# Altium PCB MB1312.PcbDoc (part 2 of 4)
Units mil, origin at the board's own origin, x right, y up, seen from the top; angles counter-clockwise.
Board outline 2755.91 x 5249.6 mil, 6 copper layers (Top Layer, GND, Signal, PWR, GND (Mid2), Bottom Layer), stack 74.545 mil thick; 297 components, 280 nets, 1142 pads, 623 vias.
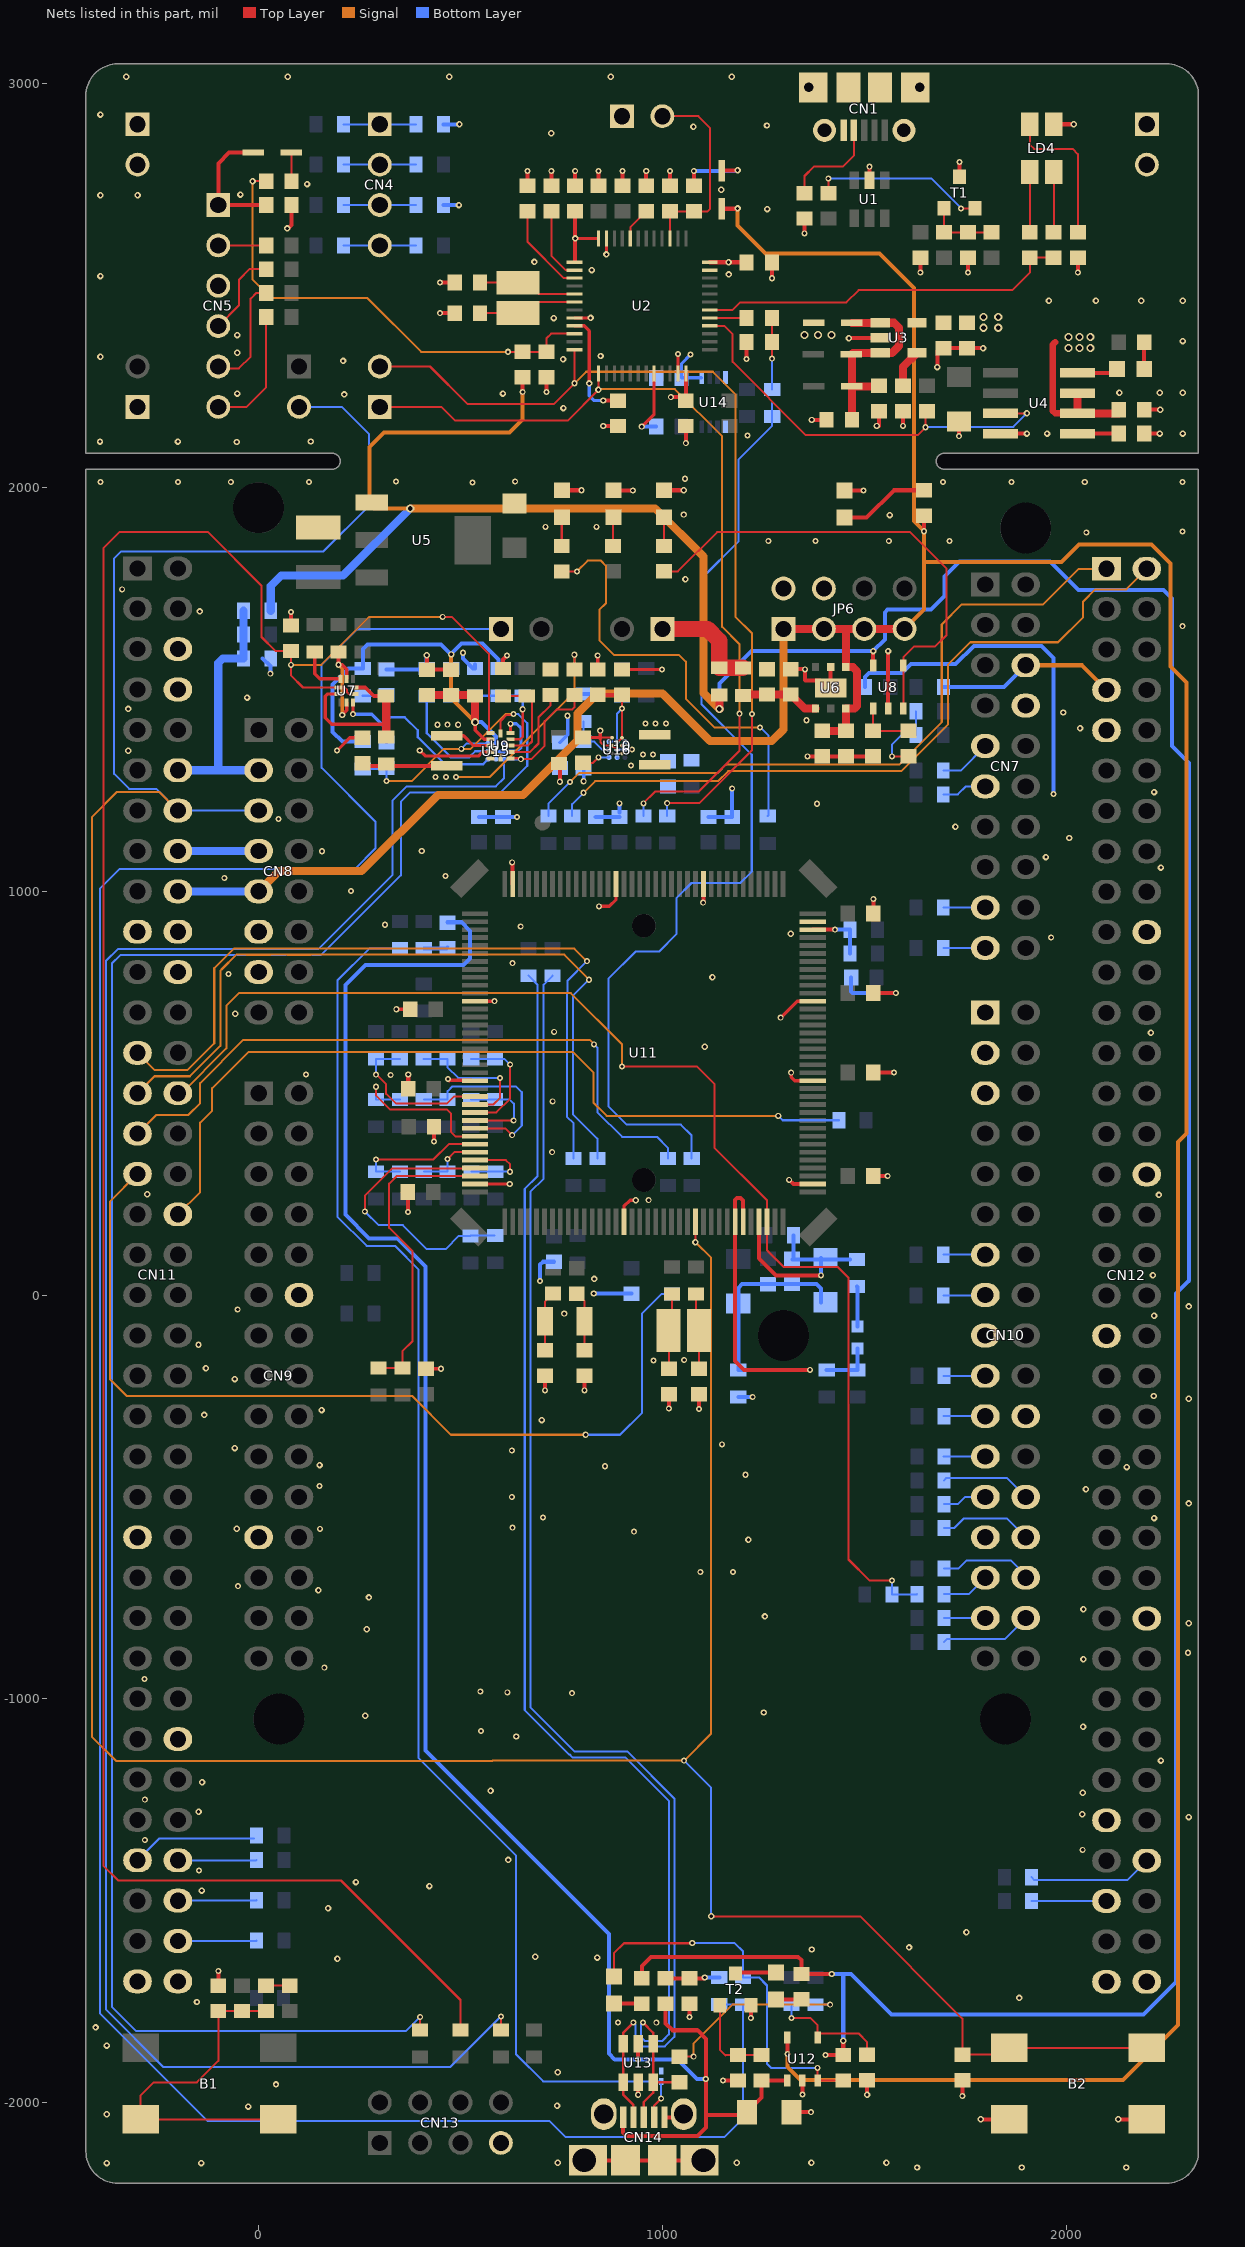
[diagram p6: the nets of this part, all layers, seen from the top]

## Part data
B1 B2: library part "SW PUSHBUTTON", "SE PUSHBUTTON"
C1 C2 C3 C4 C5 C6 C7 C8 C10 C11 C12 C13 C20 C26: library part Capacitor_ST, "Capacitor 0402 / 0603 / 0805"
C9 C14 C19 C27 C60: library part "CAP SMD 0603  X5R 1µF 25V 10%", "0603  X5R 1µ"
C15: library part "CAP SMD 0603  X7R 10000PF 50V 10%", "0603  X7R 10NF"
C16 C17 C18 C42: library part "Cap Pol1", "Polarized Capacitor (Radial)"
C21 C22 C25 C28 C29 C30 C31 C32 C33 C34 C39 C46 C47 C49 C50 C51 C53 C55 C57 C58 C61: library part Cap, "Capacitor"
C23 C24 C48: library part CAP_CC0603KRX7R9BB104, "Capacitor SMD 0603 100000pF X7R 50V +/-10%"
C35 C36 C37 C38 C40 C41: library part CAP, "Capacitor"
C43 C44 C45: library part Cap, "Capacitor,100nF,10%,16V,X7R,0603,YAGEO"
C52 C54: library part "CAP SMD 0603  X5R 1µF 25V 10%", "0603  X5R 4.7uF"
C56 C59: library part "Cap Pol1", "Tan Capacitor,1uF,10%,16V,Tan-A,TAJA105K016R"
CN2 CN3 CN6 JP1 JP2 JP3 JP4 JP5: library part JP2
CN4: "Header, 4-Pin, Single row"
CN5: "Header, 6-Pin, Single row"
CN7: "Header, 10-Pin, Dual row,female"
CN8: "Header, 8-Pin, Dual row,female"
CN9: "Header, 15-Pin, Dual row,female"
CN10: "Header, 17-Pin, Dual row,female"
CN11 CN12: "Header, 36-Pin, Dual row"
CN13: library part "Header 4X2_CN", "Header, 4-Pin, Dual row"
D2: library part Diode, "Default Diode"
D6: "Zener Diode ESDALC6V1-1U2"
JP6: "Header, 4-Pin, Dual row"
L1 L2 L3: library part Inductor, "Inductor"
LD1 LD2 LD3 LD5 LD6 LD7 LD8: library part LED2, "Typical RED, GREEN, YELLOW, AMBER GaAs LED"
LD4: "Bicolor Led"
R1 R2 R3 R4 R5 R7 R9 R10 R12 R13 R14 R15 R16 R18 R19 R20 R21 R23 R24 R25 R26 R27 R28 R50 R54: library part Resistor_ST, "Resistor 0402 / 0603 / 0805"
R6 R8 R11 R17 R22 R29 R30 R31 R32 R33 R34 R39 R40 R43 R44 R45 R52: library part Res1, "Resistor"
R35 R36 R37 R38 R41 R42 R46 R47 R48 R49 R51 R53: library part res1, "Resistor"
SB5 SB6 SB100 SB102 SB104 SB106 SB112 SB114 SB122 SB124 SB125 SB126 SB128 SB130 SB131 SB132 SB133 SB136 SB137 SB140 SB141 SB142 SB143 SB144 SB147 SB149 SB150 SB152 SB154 SB155 SB156 SB157 SB158 SB159 SB166 SB168 SB169 SB170 SB177 SB179 SB180 SB182 SB188 SB191 SB192 SB193 SB194 SB195 SB196 SB197: library part "Circuit Breaker_close", "Circuit Breaker"
SB12 SB13 SB19 SB101 SB103 SB105 SB107 SB108 SB109 SB110 SB111 SB113 SB116 SB119 SB120 SB121 SB123 SB127 SB129 SB145 SB146 SB148 SB151 SB153 SB167 SB178: library part "Circuit Breaker", "Circuit Breaker"
T1 T2: library part NPN, "NPN Bipolar Transistor"
TP1: library part TP
U2: "Medium-density performance line ARM-based 32-bit MCU with 64KB Flash"
U3: "200 mA low quiescent current very low noise LDO"
U5: library part LD1117
U6: library part LD39050P
U7: "Low voltage 0.5 O max dual SPDT switch with break-before-make"
U9: library part ST1PS022D1QTR, "400mA Nano-Quiescent?Synchronous step-down converter  with voltage selection, power good, Aux Switch"
U10: library part ST1PS01FJR, "400mA Nano-Quiescent?Synchronous step-down converter  with voltage selection and power good"
U12: library part STMPS2141STR
U15 U16: library part ADP5301, "UL Step down regulator"
X1 X3: library part XTAL, "Crystal Oscillator"
X2: library part CRYSTAL_32K, "Crystal"

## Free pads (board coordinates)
  round 125.98 hole 125.98 unplated: 0(0,1950) 0(50,-1050) 0(1300,-100) 0(1850,-1050) 0(1900,1900)

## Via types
v1: diameter 15, hole 8, Top Layer to Bottom Layer, tented both sides, 405 vias
v2: diameter 16, hole 8, Top Layer to Bottom Layer, tented both sides, 179 vias
v3: diameter 20, hole 12, Top Layer to Bottom Layer, tented both sides, 39 vias

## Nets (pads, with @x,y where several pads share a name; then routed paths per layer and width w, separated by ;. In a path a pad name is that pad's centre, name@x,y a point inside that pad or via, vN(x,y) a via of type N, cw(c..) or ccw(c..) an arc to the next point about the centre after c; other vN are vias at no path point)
+3V3: CN8.7 CN11.16 JP5.1 SB5.1 SB6.2 SB111.1 | length 523.8
  Top Layer w40: JP5.1@1000,1650 1111.85,1650 1141,1620.85 SB5.1@1141,1553.75 SB6.2@1199,1553.75
  Bottom Layer w10: 10,1577 29,1558 v1(29,1539.25)
  Bottom Layer w20: CN11.16@-200,1100 CN8.7@0,1100
+3V3_PER: R23.1 R41.2 R45.2 R51.1 SB5.2 SB110.1 U8.5 | length 9073.1
  Top Layer w10: v1(654,2236.7) R23.1@654,2273.2 ; R45.2@949,-1692.5 949,-1662 972,-1639 1336.5,-1639 1345.01,-1647.51 R41.2@1345.01,-1681.5 v1(1419.5,-1681.5) ; v1(1404,-1882) 1404.5,-1882.5 R51.1@1448,-1882.5 v1(1448,-1847) ; U8.5@1522.09,1559.15 v2(1522.09,1595)
  Top Layer w20: SB5.2@1140.75,1486 SB5.2@1141,1486.25 v3(1141,1452)
  Signal w10: v3(375.5,1948.5) 286.5,1948.5 275,1960 275,2100.94 310.06,2136 621.5,2136 654,2168.5 v1@654,2235
  Signal w20: v3(375.5,1948.5) 982.26,1948.5 1101.73,1829.03 1101.73,1491.27 v3(1141,1452)
  Bottom Layer w10: v3(1141,1452) 1141,1515 1221,1595 v2(1522.09,1595) 1551,1623.91 1551,1691 1558,1698 1665,1698 1699,1732 1699,1780 1736,1817 1960,1817 2031,1746 2241,1746 2262,1725 2262,1360.19 2304.5,1317.69 2304.5,35.5 2272.4,3.4 2272.4,-1701.6 2192,-1782 1568,-1782 1467.5,-1681.5 v1(1419.5,-1681.5) ; v1(1448,-1847) 1448,-1683.5
  Bottom Layer w20: SB110.1@30,1695 30,1756 56,1782 209,1782 v3(375.5,1948.5)
+3V3_ST_LINK: C1.2 C3.2 C8.2 C9.1 C12.2 C13.2 C43.2 JP1.1 R5.2 R13.2 SB101.2 T1.3 U2.1 U2.9 U2.24 U2.36 U2.48 U3.5 U14.1 | length 962.9
  Top Layer w8: U2.9@782.68,2400.79 806.41,2400.79 819,2388.2 v2(819,2258) ; v2(784,2617.27) 784.06,2617.32 U2.48@841.73,2617.32
  Top Layer w10: U2.1@784,2559.53 v2(784,2617.27) C1.2@784,2684.45 ; R5.2@842,2747.5 v1(842,2784) ; v1(853.5,2215.5) C12.2@890,2215.5 ; v1(1021,2224) 1049.5,2224 C13.2@1058,2215.5 ; C13.2@1058.27,2215.71 U2.24@1058.27,2282.68 ; U2.36@1117.32,2558.27 1208.24,2558.27 C3.2@1208.5,2558 v2@1170.27,2558 ; T1.3@1736,2770.37 v1(1736,2806.87) ; v1(2029,2533) R13.2@2029,2569.5
  Bottom Layer w8: v2(819,2258) 819,2227.5 831,2215.5 v1(853.5,2215.5) ; v1(1070,2330) 1047.5,2307.5 C43.2@1047.5,2272 U14.1@1096.23,2272
  Bottom Layer w10: SB101.2@457.75,2900 v2(497.25,2899.94)
  other v2: 1164,2558
  other v3: 1795,2396 1832,2396 1795,2423 1832,2423
+5V: C26.2 C27.1 CN8.9 CN11.18 D2.1 JP6.1 JP6.3 JP6.5 JP6.7 R28.2 U6.1 U6.6 U12.5 | length 9925.8
  Top Layer w10: D2.1@1147,2690.76 v2@1185.61,2690.76 ; v1(1309.6,-1879.54) U12.5@1309.6,-1838.85 ; v1(1648,1892) R28.2@1648,1930.5
  Top Layer w20: JP6.1@1300,1650 JP6.3@1400,1650 1454,1650 ; C26.2@1396,1397.5 C27.1@1455,1397.5 U6.6@1455,1452.22 ; U6.6@1454.4,1452.82 1475.82,1452.82 1482,1459 1482,1545 1471.82,1555.18 U6.1@1454.4,1555.18 1454.4,1649.6 1454,1650 ; JP6.7@1600,1650 JP6.5@1500,1650 1454,1650
  Signal w10: v2(1186.37,2691.51) 1186.37,2649.63 1256,2580 1538,2580 1623,2495 1623,1917 v1(1648,1892) 1648,1816 ; v1(1309.6,-1879.54) 1309.6,-1911.58 1342.02,-1944 2141,-1944 2277,-1808 2277,379 2298.7,400.7 2298.7,1517.3 2259,1557 2259,1812 2212,1859 2032,1859 1989,1816 1648,1816 ; JP6.7@1600,1650 1648,1698 1648,1816
  Signal w20: CN11.18@-200,995.6 CN11.18@-200,1000 ; CN8.9@-4.4,995.6 CN8.9@0,1000 50,1050 255,1050 444,1239 655,1239 790.13,1374.13 790.13,1440.87 839.26,1490 1000,1490 1118,1372 1271,1372 1300,1401 JP6.1@1300,1650 JP6.3@1400,1650 JP6.5@1500,1650 JP6.7@1600,1650
  Bottom Layer w20: CN11.18@-200,995.6 CN11.18@-200,1000 -8.8,1000 -4.4,995.6 CN8.9@0,1000
AGND: C45.2 C56.2 C57.2 C58.2 C59.2 CN10.3 CN12.32 SB166.2 U11.30 U11.31 | length 2170.9
  Top Layer w10: U11.31@1200.06,181.69 1200.06,233.94 1194,240 1185.01,240 1180.38,235.37 U11.30@1180.38,181.69 1180.38,-162.88 1202.75,-185.25 v1(1365.52,-185.25)
  Bottom Layer w10: v1(1365.52,-185.25) SB166.2@1188,-185.25 C56.2@1188,-20.5 1188,17.75 1197.55,27.3 C58.2@1321,27.3 1381.7,27.3 1393,16 C59.2@1393,-18.5 ; C45.2@1501.75,1506 1501.75,1530.52 1511.92,1540.69 1593.88,1540.69 1615.79,1562.6 1726.6,1562.6 1772,1608 1938.88,1608 1969,1577.88 v1(1969,1241)
AIN_1: R1.2 R23.2 R24.2 U2.10 | length 1188
  Top Layer w5: v2(-15,2759) R1.2@18.5,2759 ; v2(617.6,2336.2) R23.2@654,2336.2 R24.2@713,2336.2 713,2369.89 724.53,2381.42 782.68,2381.42 U2.10@782.68,2381.1
  Signal w5: v2(-15,2759) -15,2515 30.31,2469.69 268.84,2469.69 402.33,2336.2 v2(617.6,2336.2)
AVDD: C58.1 C59.1 CN10.1 SB149.1 SB152.2 U11.33 | length 506.5
  Top Layer w10: U11.33@1239.43,181.69 1239.5,181.63 1239.5,91.18 1281.68,49 v1(1393,49)
  Bottom Layer w10: SB149.1@1324.75,148 1324.75,90.45 1322.8,88.5 C59.1@1393,88.5 ; v1(1393,49) C59.1@1393,88.5 ; C59.1@1393,91.5 C59.1@1393,88.5 ; SB152.2@1465,88.5 C59.1@1393,88.5
E5V: CN11.6 D3.1 JP6.2
  other v3: 1352,2378 1385.5,2378 1419,2378
GND: B2.1 B2.4 C1.1 C2.1 C3.1 C4.1 C5.2 C6.2 C7.2 C8.1 C9.2 C10.1 C11.1 C12.1 C13.1 C14.1 C15.1 C16.2 C17.2 C18.2 C19.2 C20.1 C21.1 C22.1 C23.2 C24.2 C25.1 C26.1 C27.2 C28.2 C29.2 C30.2 C31.2 C32.2 C33.2 C34.2 C35.2 C36.2 C37.2 C38.2 C39.1 C41.1 C42.2 C43.1 C44.2 C46.1 C47.1 C48.2 C49.2 C50.2 C51.2 C52.2 C53.2 C54.2 C55.1 C60.2 C61.2 CN1.5 CN1.6 CN1.7 CN1.8 CN1.9 CN1.10 CN1.11 CN2.1 CN2.2 CN3.1 CN3.2 CN5.3 CN7.8 CN8.11 CN8.13 CN9.12 CN9.23 CN10.5 CN10.17 CN10.22 CN10.27 CN11.8 CN11.19 CN11.20 CN11.22 CN11.49 CN11.60 CN11.71 CN11.72 CN12.9 CN12.20 CN12.39 CN12.54 CN12.63 CN12.71 CN12.72 CN13.7 CN14.5 CN14.6 CN14.7 CN14.8 CN14.9 CN14.10 CN14.11 D6.2 JP2.1 LD1.2 LD2.2 LD3.2 LD4.1 LD6.2 R2.2 R3.1 R4.1 R6.2 R7.1 R10.2 R17.1 R24.1 R27.1 R32.2 R33.1 R35.1 R36.2 R38.2 R42.2 R47.2 R48.1 R52.1 R53.1 SB9.1 SB105.2 SB114.1 SB115.1 SB125.1 SB166.1 T2.2 U1.2 U2.8 U2.20 U2.23 U2.35 U2.47 U3.2 U4.4 U5.1 U6.0 U6.2 U7.8 U8.2 U9.4 U9.11 U10.A1 U10.C1 U10.D2 U11.16 U11.38 U11.51 U11.61 U11.71 U11.83 U11.94 U11.107 U11.120 U11.130 U11.143 U12.2 U13.2 U14.4 U14.5 U15.B1 U15.B2 U16.B1 U16.B2 | length 6306.4
  Top Layer w5: 846.15,1378.09 846.15,1369.85 854.9,1361.1 U10.C1@875.4,1361.1 876.32,1361.1 881.47,1355.94 883,1355.94 U10.D2@887.69,1351.26 ; 846.15,1380.78 U10.A1@875.4,1380.78
  Top Layer w8: v1(194,1348.75) 225.5,1380.25 C21.1@257.53,1380.25 ; v1(233.75,1438.75) U7.8@233.75,1467.47 ; v1(341,708) C29.2@375.5,708 ; v1(399,1348.75) 412.25,1335.5 545.5,1335.5 555.25,1345.25 U9.4@574.39,1345.25 ; C39.1@415,-182.5 v1(451.57,-182.5) ; v1@472.12,531.88 U11.130@526.71,531.88 ; U11.143@535.69,275.2 v1(622.02,275.2) v1@622.82,276 ; U11.120@535.69,727.95 v1(583.95,727.95) ; U9.11@623.61,1392.5 v1(623.61,1415) ; U2.8@782.68,2420.47 v2(822.18,2420.41) v2(822.18,2420.41) ; R35.1@803,1381.25 845.69,1381.25 ; C24.2@839.83,1549.75 v1(839.83,1584.13) ; v1(843,963) 868.84,963 885.1,979.26 U11.94@885.1,1018.31 ; 846.15,1378.09 846.15,1380.78 v1(846.15,1398.01) ; v2(861.42,2577.76) U2.47@861.42,2617.32 ; C25.1@900.31,1549.75 v1(999.25,1549.75) ; U11.16@904.79,181.69 904.79,219.79 920,235 v2(934,235) ; v1(948.98,2151) 979.53,2181.55 U2.20@979.53,2282.68 ; U2.23@1038.58,2282.68 v1@1038.58,2330.58 ; v1(1293,687) 1333.95,727.95 U11.61@1372.31,727.95 ; v1(1319,550.79) 1319,540 1327.9,531.1 U11.51@1372.31,531.1
  Top Layer w10: R42.2@-100,-1710.5 v1(-100,-1674) ; v2@73,2642 81.5,2650.5 R2.2@81.5,2700 ; R32.2@80,1658.5 v1(80,1692) ; C33.2@369.5,255 370,254.5 v1(370,206) ; C31.2@370.5,511 v1(370.5,546.02) ; v2@416.59,1584.71 C22.1@416.59,1549.25 C23.2@476.84,1549.25 ; v1(434.5,380.1) R38.2@434.5,417 ; v1(449,2432) C6.2@485.5,2432 ; v1(449,2508) C5.2@485.5,2508 ; v1(469,535) v1@472.12,531.88 ; SB9.1@605,1551.75 605,1574 v1(615,1584) ; U11.107@629.2,1018.31 v1@629.2,1070.79 ; R4.1@666,2747.5 v1(666,2784) ; v1(709,-236) C35.2@709,-199.5 ; v1(713,2236.7) R24.1@713,2273.2 ; R3.1@725,2747.5 v1(725,2784) ; LD3.2@752.75,1993.46 v1(799.75,1993.43) ; C1.1@784,2747.5 v1(784,2784) ; CN14.7@806.36,-2143.09 CN14.8@908.72,-2143.09 CN14.9@999.28,-2143.09 CN14.10@1101.64,-2143.09 ; v1(807,-236) C36.2@807,-199.5 ; v1(853.5,2152.5) C12.1@890,2152.5 ; CN14.6@866.4,-2024.2 CN14.6@879.2,-2037 ; LD2.2@879.76,1993 v1@926.73,1993 ; C2.1@901,2747.5 v1(901,2784) ; v1(940,-1980.74) U13.2@940,-1949.24 ; R7.1@960,2747.5 v1(960,2784) ; CN14.5@1005.18,-2036.79 1044.94,-2036.79 CN14.11@1052.82,-2028.91 ; LD1.2@1006,1993.47 v1@1052.97,1993.47 ; v1(1016,-281) C37.2@1016,-244.5 ; R6.2@1019,2747.5 v1(1019,2784) ; v1(1058,2110) C13.1@1058,2152.5 ; v1(1067,-1788) R47.2@1067,-1755.5 ; v1(1091,-282) C38.2@1091,-245.5 ; v1@1101.64,972.36 U11.83@1101.64,1018.31 ; v1(1150,-1945.55) 1150.05,-1945.5 R48.1@1187,-1945.5 ; v1(1208.5,2318.76) C7.2@1208.5,2361 ; v1(1219,-1791) 1219.59,-1790.41 T2.2@1219.59,-1759.37 ; v2(1271.5,2518.5) C3.1@1271.5,2558 ; v1(1314,285.5) 1324.3,275.2 U11.38@1372.31,275.2 ; C19.2@1318,1550.5 v1@1353,1550.5 ; C42.2@1320,-2024 v1(1368.36,-2024) ; v1(1347,-1980) U12.2@1347,-1945.15 ; v1(1352,2630) R10.2@1352,2666.5 ; 1353,1523.5 v1(1353,1550) v1@1354.5,1548.5 ; 1354.5,1522 U6.0@1391,1522 ; v1(1359.5,1334.5) C26.1@1396,1334.5 R36.2@1522,1334.5 ; v1(1370,2168) C10.1@1406.5,2168 ; U6.0@1417,1504 U6.2@1417,1555.18 ; LD6.2@1451.04,1992.79 v1(1498.04,1992.77) ; v2@1462,2371 U3.2@1531.85,2371 ; R52.1@1506.68,-1944.5 1506.68,-1980.68 v2(1507,-1981) ; U1.2@1513,2761.24 v1(1513,2795) ; C34.2@1522.5,295 v1(1558,295) ; C32.2@1522.5,551 v1(1574,551) ; C30.2@1522.5,748 v1(1578.18,748) ; C28.2@1522.5,945 v1@1522.5,980.5 ; v1(1531,2153) 1537,2153 C14.1@1537,2189.5 ; v2(1559,1595) 1559,1453.35 U8.2@1559.5,1452.85 ; v1(1596,2153) C15.1@1596,2189.5 ; v1(1639,2533) C4.1@1639,2569.5 ; v2(1681,2298.5) C8.1@1681,2338 ; C8.1@1696,2345.5 C9.2@1755,2345.5 v2(1794.5,2345.5) ; v1(1735,2127.5) C16.2@1735,2164 ; v1(1743,-1984) C41.1@1743,-1944.5 ; v1(1756.7,2533) R17.1@1756.7,2569.5 ; v2(1788.87,-2041.58) B2.1@1858.72,-2041.58 ; U4.4@1837.53,2134 v2(1903,2134) ; LD4.1@1969.53,2900.06 v2(2018.94,2900.06) ; v2(2129.42,-2041.58) B2.4@2199.28,-2041.58 ; R27.1@2193.5,2134 v2(2232,2134) ; C11.1@2193.5,2193 v2(2233,2193)
  Bottom Layer w5: U16.B2@887.69,1351.26 U16.B1@907.37,1351.26 v1(924.74,1351.26) v1@925,1351
  Bottom Layer w8: v1(233.75,1438.75) 280.25,1438.75 317,1402 C48.2@317,1368.5 ; U15.B2@588,1347 U15.B1@607.69,1347 639.58,1347 650,1357.42 650,1403.67 638.67,1415 v1(623.61,1415) ; C46.1@746,1368.5 765.46,1387.96 765.46,1434.54 v1(765,1435) ; SB125.1@805,1303.25 v1(805,1272.75) v1@807,1270.75
  Bottom Layer w10: R53.1@317,1549.5 SB114.1@414.05,1549.5 ; SB114.1@416.3,1551.75 v2(416.3,1585) ; SB105.2@457.75,2700 v2(496,2700) ; v1(506,1591) 506,1577.28 531.2,1552.08 SB115.1@535.6,1552.08 SB115.1@535.6,1562.08 ; C49.2@546,1184.25 C50.2@605,1184.25 v1(640.25,1184.25) ; v1(697,35) 697,75.22 704.29,82.5 C60.2@732,82.5 ; v1(830,4) 923.5,4 C61.2@924,3.5 ; C51.2@835,1184.25 C52.2@894,1184.25 ; C52.2@894,1195.5 v1(894,1218) ; v1(948.98,2151) C44.2@984.5,2151 ; C53.2@1114,1184.25 C54.2@1173,1184.25 v1(1173,1255) 1172,1254 v1@1172,1252.99 ; SB166.1@1188,-252.75 v1(1223.75,-252.75) ; C55.1@1467.5,787 1467.5,751.5 1471,748 v1(1578.18,748)
  other v1: 890,-1802 985,-1802.33 -148,-1425 2041,-1374 -282,-1350 -282,-1250 638,-1093.17 551,-1080 776,-986 616,-984 549,-982 -283,-951 162.7,-923 -51,-721 1094,-686 1175,-686 930,-586 152,-579 629,-576.21 704,-551 627,-500 151,-473 1206,-445 858,-424 627,-385.24 1148,-369.63 978,-162 1054,-161 757,-46 -52,-36 966,235 727,354 728.3,480 327,545 117.04,546.5 732,652 -75,795 629,822 1963,886 649,913 313,917.28 1101,972 1522.5,981 229.06,1001 -85,1033 463,1038 627.98,1072 157,1099.36 404,1100 49,1179 1383,1217 2288.5,1656.82 -338,1748 1262.5,1868 1379,1868 1561,1868 1711,1868 2050,1889 2288.5,1891 710.31,1903 837,1903 1053,1933 926.76,1992.97 1053,1993.44 530,2013 -391.5,2014 -199.5,2014 -69,2014 125,2014 1695,2014 1864.59,2014 2046.18,2014 2288.5,2014 340,2015 635.3,2015 1056,2022 129,2114 1211,2129 1039,2331
  other v2: 1631.03,-2161 1890,-2161 2148.97,-2161 -376.5,-2150 -142.25,-2150 741,-2149 1184,-2149 1369.21,-2149 1555,-2149 -376.5,-2029 -25.75,-2010.04 739.06,-2008 43,-1955.06 741,-1925 -376.5,-1859 -404,-1814 -153,-1751 1884,-1741 195,-1644 838.5,-1641 685,-1639 1370,-1621 1610.94,-1615.79 1753,-1578 172,-1519 -141,-1475 423,-1464 241,-1454 618,-1399 2304,-1292.86 2040,-1286 -148.74,-1279.7 2041,-1233 574.5,-1228 -140,-1206.5 2235,-1153 2042,-1069 264,-1042 1251,-1034 2043,-902 2302,-886 268,-828 2304,-813 1254,-795.84 2043,-778 273.25,-749 148,-731 1213,-606 -54,-579 2218.02,-552.5 2304,-515.94 2049,-481 2150,-426 151,-421 -59,-379 701,-309.5 -135,-297 156,-285 2304,-256.97 2217,-250 -59,-208.17 -130.5,-181.5 -149,-123 2218,-51 2304,-28 831,40 2215,49.25 2230,248 -276,250 1104.94,615 2210,650 -58,697 1124,787 1318,895 2235,1059 1950,1085 2008,1132.14 1726,1160 2218,1246 -323,1348 2034.5,1404 1357,1424 1993,1443 -323,1452 -28.66,1480 -146,1693.35 1057,1773 1563.22,1932 -54,2113 -393,2114 -200,2114 1953,2134 2289,2134 755,2197 212,2231 -53,2232.94 605,2232.94 2132,2235 2232,2235 2289,2235 209,2313.7 754,2318 -392,2323.94 847,2326 -53,2334 2289,2363 1462,2370 -53,2377.94 731,2420 1957.34,2463 2074,2463 2186,2463 2289,2463 -392,2523.94 1164.16,2528 825,2539 683,2559 71,2642 1260,2690 -392,2723.94 -300,2723.94 -45.07,2726 1146,2738 119.84,2752 725,2877.94 1077,2894 1259,2897 -392,2924 -328,3018 72,3018 472,3018 872,3018 1172,3018
IOREF: CN8.3 CN11.12 SB110.2 SB111.2 SB112.2 | length 651.9
  Bottom Layer w20: CN11.12@-200,1300 -102,1300 ; SB110.2@-37.5,1695 SB112.2@-37.5,1636 SB111.2@-37.5,1577 -89,1577 -100,1566 -100,1302 -102,1300 ; CN8.3@0,1300 -102,1300
LED_STLINK: R12.1 R18.1 U2.30 | length 927.5
  Top Layer w5: U2.30@1117.32,2440.16 1117.98,2439.5 1172.92,2439.5 1192.42,2459 1455.91,2459 1485.91,2489 1866.5,2489 1910,2532.5 R12.1@1910,2569.5 R18.1@1969,2569.5
MCO: SB109.1 SB148.2 | length 2410.7
  Bottom Layer w5: SB148.2@1072.7,338.75 1072.7,395.3 1046,422 912,422 866,468 866,783 934,851 991.79,851 1034.89,894.11 1034.89,983.4 1072.22,1020.72 1193.28,1020.72 1221.37,1048.81 1221.37,1338.63 1096.9,1463.1 1096.9,1774.9 1188,1866 1188,2069 1272,2153 SB109.1@1272,2176 1272,2209.25
NetB1_1: B1.1 B1.4 C40.2 R42.1 R43.1 | length 869
  Top Layer w5: C40.2@18,-1773.5 R43.1@-41,-1773.5 R42.1@-100,-1773.5 -100,-1897 -153,-1950 -260,-1950 -292.28,-1982.28 B1.1@-292.28,-2041.58 B1.4@48.28,-2041.58
NetC7_1: C7.1 R21.2 SB109.2 | length 176.7
  Top Layer w5: v1(1271.5,2319.5) C7.1@1271.5,2361 R21.2@1271.5,2420
  Bottom Layer w5: v1(1271.5,2319.5) 1271.5,2244 SB109.2@1272,2243.5
NetC10_2: C10.2 C14.2 D3.2 D4.2 D5.2 U3.1 U3.3 | length 520.7
  Top Layer w20: D4.2@1468.24,2330 1471.84,2333.6 U3.3@1539.72,2333.6 1568.6,2333.6 1586,2351 1586,2396 1573.6,2408.4 U3.1@1539.72,2408.4 ; D4.2@1469.24,2329 D5.2@1469.24,2251 ; D3.2@1469.24,2408 U3.1@1539.72,2408 ; C10.2@1469.5,2168 1469.24,2168.25 D5.2@1469.24,2251 ; C14.2@1535.5,2251 D5.2@1469.24,2251
NetC11_2: C11.2 JP6.4 U4.6 U4.7 | length 388.2
  Top Layer w16: 1972.75,2360 1967.17,2354.42 1967.17,2189.83 1973,2184 U4.6@2028.47,2184
  Top Layer w20: U4.7@2028.47,2234 U4.6@2028.47,2184 C11.2@2130.5,2184
  other v3: 2006,2346 2033,2346 2060,2346 2006,2373 2033,2373 2060,2373
NetC15_2: C15.2 U3.4 | length 95.3
  Top Layer w20: C15.2@1596,2252.5 1596,2299.32 U3.4@1630.28,2333.6
NetC19_1: C19.1 C20.2 SB6.1 U6.4 | length 194.9
  Top Layer w20: SB6.1@1200,1485.25 1202.25,1487.5 C20.2@1259,1487.5 C19.1@1318,1487.5 1352.69,1452.82 U6.4@1379.6,1452.82
NetC21_2: C21.2 L1.2 R34.1 SB7.1 U9.5 U15.C2 | length 723.2
  Top Layer w5: C21.2@255.23,1317.5 C21.2@257.53,1317.5 ; R34.1@782,1549.5 v1(782,1586)
  Top Layer w10: C21.2@257.53,1317.25 264.18,1310.6 L1.2@466,1310.6
  Signal w5: v1(488.73,1283.33) 572.33,1283.33 782,1493 v1(782,1586)
  other v1: 437.73,1283.33 464,1283.2
NetC22_2: C22.2 C23.1 SB8.1 SB113.1 SB116.2 SB117.2 SB129.2 U9.2 U15.A2 | length 1312.6
  Top Layer w8: v3(536.37,1419) 536.37,1399.05 558.68,1376.75 U9.2@574.39,1376.75
  Top Layer w20: C22.2@413.5,1486.5 536.37,1486.5 v3(536.37,1419)
  Signal w10: v1(477,1587) 477,1478.37 v3(536.37,1419)
  Bottom Layer w10: SB129.2@258,1370.75 207.25,1370.75 183,1395 183,1512 222.75,1551.75 SB113.1@258,1551.75 258,1600 270,1612 452,1612 v1(477,1587) ; SB116.2@477,1551.75 v1(477,1587) ; v3(536.37,1419) 552,1419 588,1383 U15.A2@588,1366.69 ; SB117.2@594.6,1552.08 594.6,1574.4 555,1614 502.84,1614 477,1588.16 v1(477,1587)
NetC24_1: C24.1 C25.2 SB120.2 SB121.2 U10.A3 U10.B2 U16.A2 U16.A3 | length 411
  Top Layer w5: U10.B2@887.69,1370.94 890.13,1370.94 U10.A3@899.97,1380.78 900.31,1381.12 v1(900.31,1453) C25.2@900.31,1486.75
  Top Layer w10: C24.1@839.83,1486.75 C25.2@900.31,1486.75
  Bottom Layer w5: U16.A3@868,1370.94 U16.A2@887.69,1370.94 887.69,1440.38 v1(900.31,1453) ; SB121.2@899.54,1484 SB121.2@899.79,1484.25 v1@899.79,1453.52
  Bottom Layer w10: SB120.2@805,1488.5 SB121.2@895.04,1488.5
NetC35_1: C35.1 R39.1 X2.2 | length 148.4
  Top Layer w5: C35.1@708.79,-136.29 X2.2@708.79,-65 708.79,-16.46 R39.1@729,3.75
NetC36_1: C36.1 R40.1 X2.1 | length 147.8
  Top Layer w5: R40.1@788,3.5 807.21,-15.71 X2.1@807.21,-65 C36.1@807.21,-136.29
NetC37_1: C37.1 SB12.1 X3.2 | length 186.8
  Top Layer w5: X3.2@1015.6,-88 1024,-79.6 SB12.1@1024,2.25 ; C37.1@1016,-181.5 X3.2@1016,-88.4
NetC38_1: C38.1 SB13.1 X3.1 | length 187.2
  Top Layer w5: SB13.1@1083,2.25 1083,-80.6 X3.1@1090.4,-88 ; C38.1@1091,-182.5 X3.1@1091,-88.6
NetC40_1: C40.1 R44.2 | length 59
  Top Layer w5: C40.1@18,-1710.5 R44.2@77,-1710.5
NetC42_1: C42.1 CN14.1 R46.1 R49.1 R54.1 U12.1 U13.5 | length 4633.9
  Top Layer w10: CN14.1@902.82,-2036.79 902.82,-2074.82 911,-2083 1087.4,-2083 1108,-2062.4 1108,-2031 ; v1(940,-1893) U13.5@940,-1854.76 ; R46.1@1008,-1755.5 1008,-1804 1025,-1821 1086.4,-1821 1108,-1842.6 v1@1108,-1942 ; v1@1108,-1941.5 1108,-2031 ; U12.1@1309.6,-1945.15 1309.25,-1945.5 R49.1@1246,-1945.5 1246,-1988 C42.1@1210,-2024 1203,-2031 1108,-2031
  Bottom Layer w10: R54.1@468,923.5 502.5,923.5 524,902 524,834 507,817 264.3,817 215,767.7 215,199 273.5,140.5 343.54,140.5 413.23,70.81 413.23,-1128.23 868,-1583 868,-1879 882,-1893 v1(940,-1893) 1037,-1893 1085.5,-1941.5 v1(1107.5,-1941.5) v1@1108,-1942
NetC46_2: C46.2 SB11.1 U9.6 | length 76.8
  Top Layer w10: v1(746,1271.47) SB11.1@746,1314.25
  Bottom Layer w10: v1(746,1271.47) C46.2@746,1305.5
NetC47_2: C47.2 L2.2 SB127.1 U10.E3 U16.C2 | length 6.7
  Top Layer w6: L2.2@976.27,1317.19 L2.2@979.55,1320.47
  Bottom Layer w6: U16.C2@887.69,1331.57 U16.C2@889.17,1330.09
  other v1: 922,1312 952,1339 977,1339
NetC48_1: C48.1 SB16.1 SB129.1 U9.12 U15.A3 | length 5537.1
  Top Layer w5: SB16.1@400,-1820.25 v1(400,-1788) ; U9.12@599,1390.53 599,1422 614.34,1437.34 635,1437.34 633.34,1439 v1(631,1439)
  Signal w5: v1(317,1273) 379,1273 459,1353 v1(502,1353) 525,1353 611,1439 v1(631,1439) 633.34,1439 v1@635,1437.34
  Bottom Layer w5: SB129.1@258,1303.25 314.75,1303.25 C48.1@317,1305.5 v1(317,1273) ; v1(400,-1788) 365.4,-1822.6 -304.12,-1822.6 -363.46,-1763.26 -363.46,821.33 -342.76,842.03 154.19,842.03 352,1039.84 352,1222 375,1245 599.22,1245 665.32,1311.1 665.32,1416.69 643,1439 v1(631,1439) ; v1(502,1353) 515.69,1366.69 U15.A3@568.31,1366.69
NetCN1_4: CN1.4 R10.1 | length 248.4
  Top Layer w5: R10.1@1352,2729.5 1352,2771.94 1375.06,2795 1447,2795 1474.41,2822.41 CN1.4@1474.41,2885
NetCN4_1: CN4.1 SB100.2 SB101.1 | length 180.5
  Bottom Layer w5: SB100.2@209.75,2900 CN4.1@300,2900 SB101.1@390.25,2900
NetCN4_2: CN4.2 SB102.2 SB103.1 | length 180.5
  Bottom Layer w5: SB102.2@209.75,2800 SB103.1@390.25,2800
NetCN4_3: CN4.3 SB104.2 SB105.1 | length 180.5
  Bottom Layer w5: SB104.2@209.75,2700 CN4.3@300,2700 SB105.1@390.25,2700
NetCN4_4: CN4.4 SB106.2 SB107.1 | length 180.5
  Bottom Layer w5: SB106.2@209.75,2600 CN4.4@300,2600 SB107.1@390.25,2600
NetCN5_1: CN5.1 D1.1 R2.1 | length 320.5
  Top Layer w5: CN5.1@-100,2700 CN5.1@-100,2700 ; D1.1@-13.24,2830 D1.1@-12.24,2829.94
  Top Layer w10: CN5.1@-100,2700 CN5.1@-100,2700 R2.1@18.5,2700 ; CN5.1@-100,2700 -100,2802.94 -72.94,2830 D1.1@-13.24,2830
NetCN5_2: CN5.2 R14.1 | length 117
  Top Layer w5: CN5.2@-100,2600 R14.1@17,2600
NetCN5_4: CN5.4 R15.1 | length 214.4
  Top Layer w5: CN5.4@-100,2400 -48.68,2451.32 -48.68,2515.32 -23,2541 R15.1@18.5,2541
NetCN5_5: CN5.5 R19.1 | length 281.7
  Top Layer w5: CN5.5@-100,2300 -95.5,2295.44 -49,2295.44 -20,2324.44 -20,2468 -6,2482 R19.1@18.5,2482
NetCN5_6: CN5.6 R20.1 | length 313.1
  Top Layer w5: CN5.6@-100,2200 -30,2199.94 18.5,2248.45 R20.1@18.5,2423
NetCN6_1: CN6.1 SB131.2 U2.13 | length 2104.4
  Top Layer w5: CN6.1@300,2200 452.53,2200 486.53,2166 765.46,2166 v2(841.73,2242.27) U2.13@841.73,2282.68 ; v1(953,1218) 981.79,1246.79 1089.53,1246.79 1191,1348.25 v1(1191,1440)
  Signal w5: v2(841.73,2242.27) 843.46,2244 1031,2244 1148,2127 1148,1655.28 1191,1612.28 v1(1191,1440) v1@1192,1439
  Bottom Layer w5: SB131.2@953,1186.75 v1(953,1218)
NetCN6_2: CN6.2 SB130.2 U2.12 | length 2253.8
  Top Layer w5: CN6.2@300,2300 424.5,2300 517.5,2207 731,2207 v1(782.5,2258.5) 782.68,2258.68 U2.12@782.68,2341.73 ; v1(1012,1218.3) 1091.3,1218.3 1222,1349 v1(1222,1439)
  Signal w5: v1(782.5,2258.5) 811,2287 1125,2287 1181,2231 1181,1680 1222,1639 v1(1222,1439)
  Bottom Layer w5: SB130.2@1012,1186.75 v1(1012,1218.3)
NetCN7_6: CN7.6 CN12.7 SB119.2 | length 451.6
  Signal w10: CN7.6@1900,1560 2039,1560 CN12.7@2100,1499
  Bottom Layer w10: SB119.2@1696,1506 1846,1506 CN7.6@1900,1560
NetCN7_9: CN7.9 SB126.2 | length 129.5
  Bottom Layer w5: SB126.2@1695.75,1299 1739,1299 CN7.9@1800,1360
NetCN7_11: CN7.11 SB128.2 | length 112.5
  Bottom Layer w5: SB128.2@1695.75,1240 1732,1240 1752,1260 CN7.11@1800,1260
NetCN7_17: CN7.17 SB133.2 | length 104.3
  Bottom Layer w5: SB133.2@1695.75,960 CN7.17@1800,960
NetCN7_19: CN7.19 SB140.2 | length 104.3
  Bottom Layer w5: SB140.2@1695.75,860 CN7.19@1800,860
NetCN10_13: CN10.13 SB150.2 | length 104.3
  Bottom Layer w5: SB150.2@1695.75,100 CN10.13@1800,100
NetCN10_15: CN10.15 SB155.2 | length 104.7
  Bottom Layer w5: SB155.2@1695.75,-1 1799,-1 CN10.15@1800,0
NetCN10_19: CN10.19 SB157.2 | length 104.3
  Bottom Layer w5: SB157.2@1695.75,-200 CN10.19@1800,-200
NetCN10_21: CN10.21 SB159.2 | length 104.3
  Bottom Layer w5: SB159.2@1695.75,-300 CN10.21@1800,-300
NetCN10_23: CN10.23 SB168.2 | length 113.6
  Top Layer w5: CN10.23@1800,-408.28 CN10.23@1800,-400
  Bottom Layer w5: SB168.2@1695.75,-400 CN10.23@1800,-400 CN10.23@1799.25,-399.25
NetCN10_25: CN10.25 SB170.2 | length 109.7
  Bottom Layer w5: SB170.2@1697.75,-518 1732.06,-518 1750.06,-500 CN10.25@1800,-500
NetCN10_26: CN10.26 SB169.1 | length 224.2
  Bottom Layer w5: SB169.1@1697.75,-459 1703.75,-453 1853,-453 CN10.26@1900,-500
NetCN10_28: CN10.28 SB177.1 | length 230.8
  Bottom Layer w5: SB177.1@1697.75,-577 1722.8,-577 1745.8,-554 1854,-554 CN10.28@1900,-600
NetCN10_29: CN10.29 SB179.2 | length 119.2
  Bottom Layer w5: SB179.2@1697.75,-741 1759,-741 CN10.29@1800,-700
NetCN10_30: CN10.30 SB180.1 | length 230.6
  Bottom Layer w5: SB180.1@1698,-677 1734,-677 1753.03,-657.97 1863.7,-657.97 1900,-694.27 CN10.30@1900,-700
NetCN10_31: CN10.31 SB182.2 | length 102.3
  Bottom Layer w5: SB182.2@1697.75,-800 CN10.31@1800,-800
NetCN10_32: CN10.32 SB188.1 | length 226.7
  Bottom Layer w5: SB188.1@1697.75,-859 1704.75,-852 1848,-852 CN10.32@1900,-800
NetCN11_25: CN11.25 SB145.2 | length 1893
  Signal w5: CN11.25@-300,600 -257.03,557.03 -176.4,557.03 -110,623.43 -110,809.66 -61.66,858 -23.34,858 ; -23.31,857.97 23.31,857.97 ; 23.34,858 76.66,858 ; 76.69,857.97 123.31,857.97 ; 123.34,858 782,858 v1(813,827)
  Bottom Layer w5: SB145.2@780,338.75 780,425.29 763.5,441.79 763.5,747.71 765,749.21 765,779 v1(813,827)
NetCN11_27: CN11.27 SB146.2 | length 1879.2
  Signal w5: CN11.27@-300,500 -257.97,542.03 -170.19,542.03 -95,617.21 -95,803.28 -92.07,806.22 -92.07,806.38 -55.44,843 -29.55,843 ; -29.53,842.97 29.53,842.97 ; 29.55,843 70.45,843 ; 70.47,842.97 129.53,842.97 ; 129.55,843 757.06,843 818,782.06 v1(818,781)
  Bottom Layer w5: v1(818,781) 778.5,741.5 778.5,448 839,387.5 SB146.2@839,338.75
NetCN11_29: CN11.29 SB147.2 | length 1669.2
  Signal w5: CN11.29@-300,400 -254,446 -174.25,446 -145,475.25 -145,524.79 -37.84,631.95 819.95,631.95 v1(830.9,621)
  Bottom Layer w5: v1(830.9,621) 838.88,613.02 838.88,453 900.18,391.69 986.78,391.69 1013.7,364.77 SB147.2@1013.7,338.75
NetCN11_31: CN11.31 SB156.2 | length 2273.9
  Signal w5: CN11.31@-300,300 -367.8,232.2 -367.8,-209.2 -327,-250 380,-250 476,-346 v1(810,-346)
  Bottom Layer w5: v1(810,-346) 895,-346 950,-291 950,-45.38 997.63,2.25 SB156.2@1024,2.25
NetCN11_34: CN11.34 SB144.1 | length 2050.7
  Signal w5: CN11.34@-200,200 -145,255 -145,427 -115,457 -115,512.36 -25.41,601.95 778.83,601.95 829.16,551.62 829.16,476.94 862.1,444 v1(1287,444)
  Bottom Layer w5: v1(1287,444) 1298,433 SB144.1@1437.25,433
NetCN11_65: CN11.65 SB191.2 | length 310.4
  Bottom Layer w5: CN11.65@-300,-1400 -246,-1346 SB191.2@-12,-1346
NetCN11_66: CN11.66 SB192.1 | length 195.4
  Bottom Layer w5: CN11.66@-200,-1400 -6,-1400 SB192.1@-5,-1399
NetCN11_68: CN11.68 SB194.1 | length 195.4
  Bottom Layer w5: CN11.68@-200,-1500 -6,-1500 SB194.1@-5,-1499
NetCN11_70: CN11.70 SB196.1 | length 195.4
  Bottom Layer w5: CN11.70@-200,-1600 -96,-1600 -6,-1600 SB196.1@-5,-1599
NetCN12_1: CN12.1 SB136.2 | length 1797.3
  Signal w5: v1(771,1270.75) 793.25,1293 1136.57,1293 1158.08,1314.5 1587.5,1314.5 1692,1419 1692,1661 1742,1711 1943,1711 2031,1799 CN12.1@2100,1799
  Bottom Layer w5: SB136.2@717.7,1186.5 717.7,1217.45 v1(771,1270.75) ; CN12.1@2098.97,1800.03 CN12.1@2100,1799
NetCN12_2: CN12.2 SB137.2 | length 1804.1
  Signal w5: v1(804.77,1244.23) 833.54,1273 1137.79,1273 1162.79,1298 1592.21,1298 1707,1412.79 1707,1561 1763.03,1617.03 1929.53,1617.03 ; 1929.55,1617 1980,1617 2042,1679 2042,1718 2072,1748 2149,1748 CN12.2@2200,1799
  Bottom Layer w5: SB137.2@776.7,1186.5 776.7,1216.16 v1(804.77,1244.23)
NetCN12_66: CN12.66 SB193.1 | length 308.3
  Bottom Layer w5: SB193.1@1914.5,-1442 1921.5,-1449 2152,-1449 CN12.66@2200,-1401
NetCN12_67: CN12.67 SB195.2 | length 185.5
  Bottom Layer w5: SB195.2@1914.5,-1501 CN12.67@2100,-1501
NetCN14_2: CN14.2 SB142.1 U13.1 U13.6 | length 3289.2
  Top Layer w6.1: v1(928.05,-1802) 902.6,-1827.45 U13.6@902.6,-1854.76 U13.1@902.6,-1949.24 902.6,-1980.36 928.41,-2006.17 CN14.2@928.41,-2036.79
  Bottom Layer w5: SB142.1@728,791 705.78,768.78 705.78,288.46 673,255.67 673,-1021 783,-1131 914,-1131 1029.9,-1246.9 1029.9,-1837.1 1006,-1861 950.32,-1861 933.08,-1843.76 933.08,-1807.02 v1(928.05,-1802)
NetCN14_3: CN14.3 R50.1 SB143.1 U13.3 U13.4 | length 3307.7
  Top Layer w6.1: v1@950.67,-1803.33 953.33,-1803.33 977.4,-1827.4 U13.4@977.4,-1854.76 U13.3@977.4,-1949.24 ; CN14.3@954,-2036.79 954,-1999 977.4,-1975.6 U13.3@977.4,-1949.24 ; R50.1@1041.75,-1949.24 U13.3@977.4,-1949.24
  Bottom Layer w5: SB143.1@668.57,791 690.78,768.78 690.78,294.67 659.1,262.99 659.1,-1028.31 768.32,-1137.54 769.88,-1137.54 777.24,-1144.9 908.24,-1144.9 1016,-1252.66 1016,-1831.34 1000.24,-1847.1 956.07,-1847.1 946.98,-1838 946.98,-1807.02 v1(952,-1802)
NetCN14_4: CN14.4 D6.1 SB134.1 | length 3555.4
  Top Layer w5: CN14.4@979.59,-2036.79 979.59,-2007.41 v1(997,-1990)
  Bottom Layer w5: SB134.1@350,858.25 274.05,858.25 194.9,779.1 194.9,194.35 267.61,121.64 337.64,121.64 395.73,63.56 395.73,-1146.51 638,-1388.79 638,-1881 704.8,-1947.8 D6.1@997,-1947.8 v1(997,-1990)
NetD1_2: D1.2 R1.1 | length 71.1
  Top Layer w5: D1.2@81.24,2830 81.5,2829.75 R1.1@81.5,2759
NetD2_2: D2.2 R8.1 | length 187.1
  Top Layer w10: R8.1@1078,2747.5 v1(1078,2784) ; D2.2@1147,2785.24 v2@1185.61,2785.24
  Bottom Layer w5: v2@1184.43,2787.94 v2(1186.37,2786)
  Bottom Layer w10: v1(1078,2784) 1184.37,2784 v2(1186.37,2786)
NetJP1_2: JP1.2 R6.1 R8.2 U2.39 | length 499.4
  Top Layer w5: JP1.2@1000,2920 1089,2920 1118.46,2890.54 1118.46,2691 1111.96,2684.5 R8.2@1078,2684.5 ; U2.39@1018.9,2617.27 U2.39@1018.9,2617.32 R6.1@1018.9,2684.34 ; R6.1@1019,2684.45 R8.2@1078,2684.45
NetJP4_1: JP4.1 SB198.2 SB199.1 | length 6580.4
  Bottom Layer w5: JP4.1@600,1650 245,1650 156,1561 156,1306 289,1173 289,1106.1 238.8,1055.9 -344.3,1055.9 -393.46,1006.74 -393.46,-1778.66 -126.11,-2046 721,-2046 761,-2086 1153,-2086 1200,-2039 SB198.2@1200,-1757.75 1141.06,-1757.75 SB199.1@1141,-1757.69
NetL1_1: L1.1 U9.3 U15.A1 | length 120
  Top Layer w8: L1.1@466,1385.4 507.69,1385.4 532.09,1361 U9.3@574.39,1361
  Bottom Layer w6: U15.A1@606.2,1366.69 U15.A1@607.69,1366.69
  other v1: 443.27,1412.67 468,1412.8 494.27,1412.67
NetL2_1: L2.1 U10.C3 U16.A1
  other v1: 958.27,1415.67 983,1415.8 1009.27,1415.67
NetL3_1: L3.1 SB158.2 SB167.2 | length 129
  Bottom Layer w10: SB158.2@1407,-185.25 SB167.2@1483,-185.25 1483.53,-184.72 L3.1@1483.53,-132.5
NetL3_2: L3.2 SB152.1 | length 99.1
  Bottom Layer w10: SB152.1@1482,21 1483.53,19.47 L3.2@1483.53,-77.5
NetLD1_1: LD1.1 R31.2 | length 71
  Top Layer w5: R31.2@1004,1855.5 LD1.1@1004,1926.54
NetLD2_1: LD2.1 R30.2 | length 70.7
  Top Layer w5: LD2.1@877.76,1926.07 878,1925.83 R30.2@878,1855.5
NetLD3_1: LD3.1 R29.2 | length 71.1
  Top Layer w5: R29.2@750.75,1855.46 LD3.1@750.75,1926.53
NetLD4_2: LD4.2 R18.2 | length 149.7
  Top Layer w5: R18.2@1969,2632.5 1969.53,2633.02 LD4.2@1969.53,2781.94
NetLD4_3: LD4.3 R12.2 | length 149.6
  Top Layer w5: R12.2@1910,2632.5 1910.47,2632.97 LD4.3@1910.47,2781.94
NetLD4_4: LD4.4 R13.1 | length 372.3
  Top Layer w5: LD4.4@1910.47,2900.06 1910.47,2849.53 1921,2839 2016,2839 2029,2826 R13.1@2029,2632.5
NetLD5_1: LD5.1 R22.2 | length 66
  Top Layer w10: LD5.1@2193.5,2294.03 R22.2@2193.5,2360
NetLD5_2: LD5.2 U4.8 | length 98.1
  Top Layer w10: U4.8@2028.47,2284 LD5.2@2126.54,2284
NetLD6_1: LD6.1 R28.1 | length 225
  Top Layer w10: LD6.1@1451.04,1925.86 1505.86,1925.86 1573.5,1993.5 R28.1@1648,1993.5
NetLD7_1: LD7.1 R45.1 | length 68
  Top Layer w10: LD7.1@880,-1754.46 R45.1@947.97,-1754.46
NetLD7_2: LD7.2 R51.2 SB198.1 U12.3 | length 947
  Top Layer w5: LD7.2@880,-1687.53 880,-1630.53 905,-1605.53 1073.47,-1605.53 v1(1074,-1605) ; v1(1384.4,-1914) U12.3@1384.4,-1945.15 1384,-1945.55 1447.95,-1945.55 R51.2@1448,-1945.5
  Bottom Layer w5: v1(1074,-1605) 1179,-1605 1200,-1626 SB198.1@1200,-1690.25 1239.25,-1690.25 1259.12,-1710.12 1259.12,-1904.12 1269,-1914 v1(1384.4,-1914)
NetLD8_1: LD8.1 R41.1 | length 64
  Top Layer w10: LD8.1@1281.01,-1744.47 R41.1@1344.97,-1744.47
NetLD8_2: LD8.2 T2.3 | length 101.3
  Top Layer w10: T2.3@1181.01,-1680.63 1184.1,-1677.54 LD8.2@1281.01,-1677.54
NetR3_2: R3.2 U2.2 | length 183.1
  Top Layer w5: R3.2@725,2684.77 R3.2@725,2684.5 725,2574 760.48,2538.53 U2.2@782.68,2538.58
NetR4_2: R4.2 U2.3 | length 229.5
  Top Layer w5: R4.2@666,2684.5 666,2608.94 756.04,2518.9 U2.3@782.68,2518.9
NetR7_2: R7.2 U2.44 | length 83.7
  Top Layer w5: U2.44@920.47,2617.27 920.47,2644.61 R7.2@960.32,2684.45
NetR9_2: R9.2 T1.2 | length 427.9
  Top Layer w5: R9.2@1411,2729.5 v1@1411,2763 ; v1(1739.93,2691.63) T1.2@1774.58,2691.63
  Bottom Layer w5: v1(1411,2766) 1665.56,2766 v1(1739.93,2691.63)
NetR11_1: R11.1 R16.1 R17.2 T1.1 | length 176.9
  Top Layer w5: T1.1@1697.7,2691.35 R16.1@1697.7,2632.5 R11.1@1815.7,2632.5
NetR21_1: R21.1 U2.29 | length 90.8
  Top Layer w5: U2.29@1117.32,2420.47 R21.1@1208.09,2420.41
NetR26_2: R26.2 U2.28 U4.3 | length 1058.8
  Top Layer w5: U2.28@1117.32,2400.79 1153.11,2400.79 1174,2379.9 1174,2311.45 1355.45,2130 1632.5,2130 v1(1652,2149.5) R26.2@1652,2186 ; U4.3@1837.53,2184 v2(1903,2184)
  Bottom Layer w5: v1@1655,2150.6 1869.6,2150.6 v2(1903,2184)
NetR27_2: R27.2 U4.5 | length 92.8
  Top Layer w10: U4.5@2028.47,2134 R27.2@2121.31,2134
NetR29_1: R29.1 SB132.2 | length 1087.2
  Top Layer w5: R29.1@750.75,1792.47 v1(788.47,1792.47)
  Signal w5: v1(788.47,1792.47) 815,1819 848,1819 860,1807 860,1713 844,1697 844,1622 880,1586 1041,1586 1058,1569 1058,1477 1129,1406 v1(1242,1406)
  Bottom Layer w5: v1(1242,1406) 1263,1385 1263,1188.5 SB132.2@1261,1186.5
NetR31_1: R31.1 U8.3 U8.4 | length 1196.6
  Top Layer w5: R31.1@1006,1792.5 1038.5,1792.5 1135.5,1889.5 1613.5,1889.5 1704,1799 1704,1635 1675,1606 1623,1606 1596.9,1579.9 U8.4@1596.9,1559.15 U8.3@1596.9,1452.85
NetR32_1: R32.1 SB17.1 U7.4 U7.9 U9.1 | length 6053.9
  Top Layer w5: U7.9@237.69,1489.13 222.88,1489.13 219,1493 219,1499 213.13,1504.87 U7.4@198.32,1504.87 109.88,1504.87 80,1534.75 v1(80,1561) R32.1@80,1595.5 41.5,1595.5 7,1630 7,1757 -126.6,1890.6 -344,1890.6 -384.5,1850.1 -384.5,-1413.2 -347.7,-1450 204,-1450 500,-1746 SB17.1@500,-1820.25 ; v1(455.9,1680) 478.82,1680 570,1588.82 570,1396.89 U9.1@574.39,1392.5
  Signal w5: v1(80,1561) 155.18,1561 274.18,1680 v1(455.9,1680)
NetR33_2: R33.2 U9.8 | length 210.9
  Top Layer w5: U9.8@623.61,1345.25 672.29,1345.25 693.18,1366.15 693.18,1431.18 723,1461 R33.2@723,1486.5
NetR34_2: R34.2 SB18.1 U9.7 U15.C1 | length 5367.9
  Top Layer w5: SB18.1@600,-1820.25 v1(600,-1787) ; v1(649.32,1327.32) 675.57,1327.32 708.39,1360.14 708.39,1421.39 738,1451 777,1451 782,1456 R34.2@782,1486.5
  Top Layer w6: U9.7@623.61,1329.5 v1@649.32,1329.5
  Bottom Layer w5: v1(600,-1787) 475,-1912 -235.93,-1912 -378.46,-1769.47 -378.46,827.54 -348.97,857.03 147.98,857.03 331,1040.05 331,1224 367,1260 587.73,1260 607.69,1279.96 U15.C1@607.69,1327.32
  Bottom Layer w6: U15.C1@607.69,1327.32 v1(649.32,1327.32)
NetR35_2: R35.2 U16.C3 | length 70.9
  Top Layer w5: R35.2@803,1318.25 828.25,1318.25 v1(842,1332)
  Bottom Layer w5: v1(842,1332) 867.57,1332 U16.C3@868,1331.57
NetR36_1: R36.1 R37.1 U8.1 | length 143.4
  Top Layer w5: U8.1@1522.09,1452.85 1522.09,1397.59 R36.1@1522,1397.5 R37.1@1610,1397.5
NetR37_2: R37.2 SB123.1 SB124.2 | length 198.4
  Top Layer w5: v1(1569,1334.5) R37.2@1610,1334.5
  Bottom Layer w5: v1(1569,1334.5) 1569,1364 1592,1387 SB123.1@1628.25,1387 1628.25,1445.75 SB124.2@1628.5,1446
NetR46_2: R46.2 R47.1 SB199.2 | length 134
  Top Layer w10: R46.2@1008,-1692.5 R47.1@1067,-1692.5 1102.68,-1692.5 v1(1105,-1690.19)
  Bottom Layer w10: v1(1105,-1690.19) SB199.2@1141,-1690.19
NetR48_2: R48.2 R49.2 T2.1 | length 219.5
  Top Layer w5: T2.1@1142.42,-1759.37 1142.42,-1869.42 1156,-1883 1156.5,-1882.5 R48.2@1187,-1882.5 R49.2@1246,-1882.5
NetR50_2: R50.2 SB201.2 | length 483.2
  Top Layer w5: R50.2@1042,-1886.5 v1(1077.5,-1886.5)
  Signal w5: v1(1077.5,-1886.5) 1077.5,-1853.5 1173.25,-1757.75 v1(1415.75,-1757.75)
  Bottom Layer w5: SB201.2@1379,-1757.75 v1(1415.75,-1757.75)
NetR52_2: R52.2 SB200.2 U12.4 | length 298.6
  Top Layer w5: v1(1320,-1791) 1367,-1791 1384.4,-1808.4 U12.4@1384.4,-1830.6 ; U12.4@1384.4,-1838.85 U12.4@1384.4,-1830.6 ; R52.2@1506.68,-1881.5 1506.68,-1849.68 1486,-1829 1386,-1829 U12.4@1384.4,-1830.6
  Bottom Layer w5: v1(1320,-1791) SB200.2@1320,-1757.75
NetR53_2: R53.2 SB113.2 U15.C3 | length 425.2
  Bottom Layer w6: SB113.2@258,1484.25 314.75,1484.25 R53.2@317,1486.5 317,1439 325,1431 362,1431 394.09,1398.91 394.09,1382.09 461.38,1314.81 555.81,1314.81 U15.C3@568.31,1327.32
NetR54_2: R54.2 SB135.1 | length 59.9
  Bottom Layer w10: SB135.1@409,858.25 465.75,858.25 R54.2@468,860.5
NetSB1_1: SB1.1 U7.3 | length 122.7
  Top Layer w9: SB1.1@139,1593.25 139,1539 151.47,1526.53 U7.3@202.25,1526.53
NetSB2_1: SB2.1 U7.2 U7.7 | length 243.8
  Top Layer w9: v1(197.77,1561.23) 198.44,1561.23 206.77,1561.23 218,1550 U7.2@218,1526.53 ; v1(207,1437) 207,1437.46 218,1448.46 U7.7@218,1467.47
  Top Layer w10: SB2.1@197.77,1593.31 197.77,1561.89 v1@198.44,1561.23
  Signal w9: v1(197.77,1561.23) 207,1552 v1(207,1437)
NetSB4_1: SB4.1 SB7.2 U7.5 U7.10 | length 477.5
  Top Layer w8: U7.5@198.32,1489.13 170.63,1489.13 165,1483.5 165,1430 181,1414 309,1414 315,1420 315,1383.5 SB7.2@316,1382.5 ; SB7.2@315,1379.25 SB7.2@315,1382.75
  Top Layer w9: U7.10@237.69,1504.87 264.13,1504.87 285,1484 SB4.1@315,1484
  Top Layer w20: SB4.1@315,1484 316,1483 SB7.2@316,1382.5
NetSB9_2: SB9.2 SB10.2 U9.9 | length 235.1
  Top Layer w5: SB9.2@595,1484.25 SB10.2@654,1484.25 ; U9.9@623.61,1361 666.83,1361 677,1371.17 677,1471.25 SB10.2@664,1484.25
NetSB14_2: SB14.2 SB15.1 U11.142 | length 770.1
  Top Layer w5: SB14.2@297,-180.25 SB15.1@356,-180.25 356,-139 381,-114 381,108.39 323,166.39 323,276 341.88,294.88 U11.142@535.69,294.88
NetSB114_2: SB114.2 SB116.1 U15.B3 | length 353.3
  Bottom Layer w6: SB114.2@404,1471.95 415.99,1483.94 SB114.2@415.99,1484.56 ; SB116.1@477,1484.25 SB114.2@416.3,1484.25 416.3,1392 475.88,1332.42 522,1332.42 536.58,1347 U15.B3@568.31,1347
NetSB115_2: SB115.2 SB117.1 SB118.2 U9.10 | length 252.8
  Top Layer w6: U9.10@623.61,1376.75 647.75,1376.75 654,1383 v1(654,1451)
  Bottom Layer w6: SB115.2@526.6,1484.58 SB115.2@535.6,1484.58 SB118.2@644.92,1484.58 ; v1(654,1451) SB118.2@654,1484.5
NetSB120_1: SB120.1 SB125.2 U16.B3 | length 121.3
  Bottom Layer w5: SB120.1@805,1421 SB125.2@805,1370.75 831.61,1370.75 851.11,1351.26 U16.B3@868,1351.26
NetSB138_1: SB138.1 SB139.1 U11.70 | length 152
  Top Layer w10: U11.70@1372.31,905.12 v1(1427.88,905.12)
  Bottom Layer w10: v1(1427.88,905.12) 1465.13,905.12 SB138.1@1465.25,905 SB139.1@1465.25,846
NetSB160_1: SB160.1 SB161.1 U11.132 | length 392.6
  Top Layer w5: v1(291,546) 292,546 316,522 316,498.47 340.37,474.1 466.1,474.1 483.73,491.73 U11.132@535.69,491.73
  Bottom Layer w5: v1@290.53,547 SB160.1@290.53,585 SB161.1@349.53,585
NetSB162_1: SB162.1 SB164.1 U11.133 | length 342.9
  Top Layer w5: U11.133@535.69,472.05 581.05,472.05 598,489 v1(598,538) 600,538 v1@601,537
  Bottom Layer w5: SB162.1@408.53,584.98 467.26,584.98 SB164.1@467.53,585.25 467.53,564.76 494.28,538 v1(598,538)
NetSB163_1: SB163.1 SB165.1 U11.134 | length 288.4
  Top Layer w5: U11.134@535.69,452.36 589,452.36 623,486.37 v1(623,571)
  Bottom Layer w5: SB163.1@526.53,585.25 SB165.1@585.53,585.25 608.75,585.25 v1(623,571)
NetSB171_1: SB171.1 SB172.1 U11.137 | length 425.7
  Top Layer w5: v1(291,516) 291,494 325.9,459.1 466.9,459.1 476.15,449.85 476.15,404.15 487,393.31 U11.137@535.69,393.31
  Bottom Layer w5: v1(291,516) SB171.1@291,484.5 SB172.1@350,484.5
NetSB173_1: SB173.1 SB174.1 U11.136 | length 490
  Top Layer w5: U11.136@535.69,412.99 610.99,412.99 v1(627.98,396)
  Bottom Layer w5: SB173.1@409,484.5 SB174.1@468,484.5 468,505 480.1,517.1 637.25,517.1 651.68,502.68 651.68,419.7 v1(627.98,396)
NetSB175_1: SB175.1 SB176.1 U11.135 | length 247.8
  Top Layer w5: U11.135@535.69,432.68 v1(631.68,432.68) v1@632,433
  Bottom Layer w5: SB175.1@526.53,485 620.98,485 632,473.98 v1@632,432.68
NetSB181_1: SB181.1 SB186.1 U11.139 | length 165.2
  Top Layer w5: v1(468,337) 484.94,353.94 U11.139@535.69,353.94
  Bottom Layer w5: SB181.1@409,305.5 SB186.1@468,305.5 v1(468,337)
NetSB183_1: SB183.1 SB184.1 U11.138 | length 350.1
  Top Layer w5: v1(291,336) 433,336 471,374 535.32,374 U11.138@535.69,373.62
  Bottom Layer w5: v1(291,336) SB183.1@291,305.5 SB184.1@350,305.5
NetSB185_1: SB185.1 SB187.1 U11.140 | length 205.4
  Top Layer w5: U11.140@535.69,334.25 535.95,334 612.33,334 622.82,323.51 v1(622.82,305.5)
  Bottom Layer w5: SB185.1@527,305.5 SB187.1@586,305.5 v1(622.82,305.5)
NetSB189_2: SB189.2 SB190.2 U11.141 | length 712.9
  Top Layer w5: v1(263,207) 263,245.75 331.25,314 535.13,314 U11.141@535.69,314.57
  Bottom Layer w5: v1(263,207) 297,173 357,173 416,114 463.06,114 495.56,146.5 SB189.2@525,146.5 ; SB189.2@525,147 SB190.2@584,147
NRST: B2.2 B2.3 C41.2 CN8.5 CN11.14 JP3.2 U11.25 | length 9105.9
  Top Layer w5: v2@1081.95,134 U11.25@1081.95,181.69 ; v1@1121.32,-1539 1490,-1539 1743,-1792 C41.2@1743,-1881.5 B2.2@1841.64,-1881.5 ; B2.2@1830,-1835.69 B2.2@1858.72,-1864.42 B2.3@2199.28,-1864.42
  Signal w5: CN11.14@-200,1200 -246,1246 -351,1246 -412.95,1184.05 -412.95,-1094.05 -353,-1154 577.97,-1154 578.67,-1153.3 v1(1053.7,-1153.3) 1121,-1086 1121,92 v2(1082,131)
  Bottom Layer w5: CN8.5@0,1200 CN11.14@-200,1200 -254,1254 -321,1254 -358,1291 -358,1824.64 -340.61,1842.03 160.69,1842.03 272.8,1954.14 272.8,2133.2 206,2200 JP3.2@100,2200 ; v1(1053.7,-1153.3) 1121,-1220.6 v1(1121,-1538.68)
OSC_IN: C5.1 U2.5 X1.2 | length 245.1
  Top Layer w5: C5.1@548.5,2508 X1.2@641.4,2508 ; X1.2@642,2507.4 665.6,2507.4 693.47,2479.53 U2.5@782.68,2479.53
OSC_OUT: C6.1 U2.6 X1.1 | length 245.1
  Top Layer w5: C6.1@548.5,2432 X1.1@641.4,2432 ; X1.1@642,2432.6 665.6,2432.6 692.84,2459.84 U2.6@782.68,2459.84 U2.6@782.52,2460
PA0: CN11.28 SB178.2 SB179.1 U11.34 | length 3242.3
  Top Layer w5: v1(900,566) 1086,566 1129,523 1129,365 1259.12,234.88 U11.34@1259.12,181.69 1259.12,110.88 1300,70 1433.82,70 1461,42.82 1461,-655 1513.25,-707.25 v1(1568.75,-707.25)
  Signal w5: CN11.28@-200,500 -191,500 -80,611 -80,717 -49.05,747.95 773.26,747.95 900,621.21 v1(900,566)
  Bottom Layer w5: SB178.2@1568.75,-742 SB178.2@1568.75,-741.7 ; v1@1571,-705 v1(1568.75,-707.25) SB178.2@1568.75,-741.7 ; SB179.1@1630.25,-741 1629.55,-741.7 SB178.2@1568.75,-741.7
